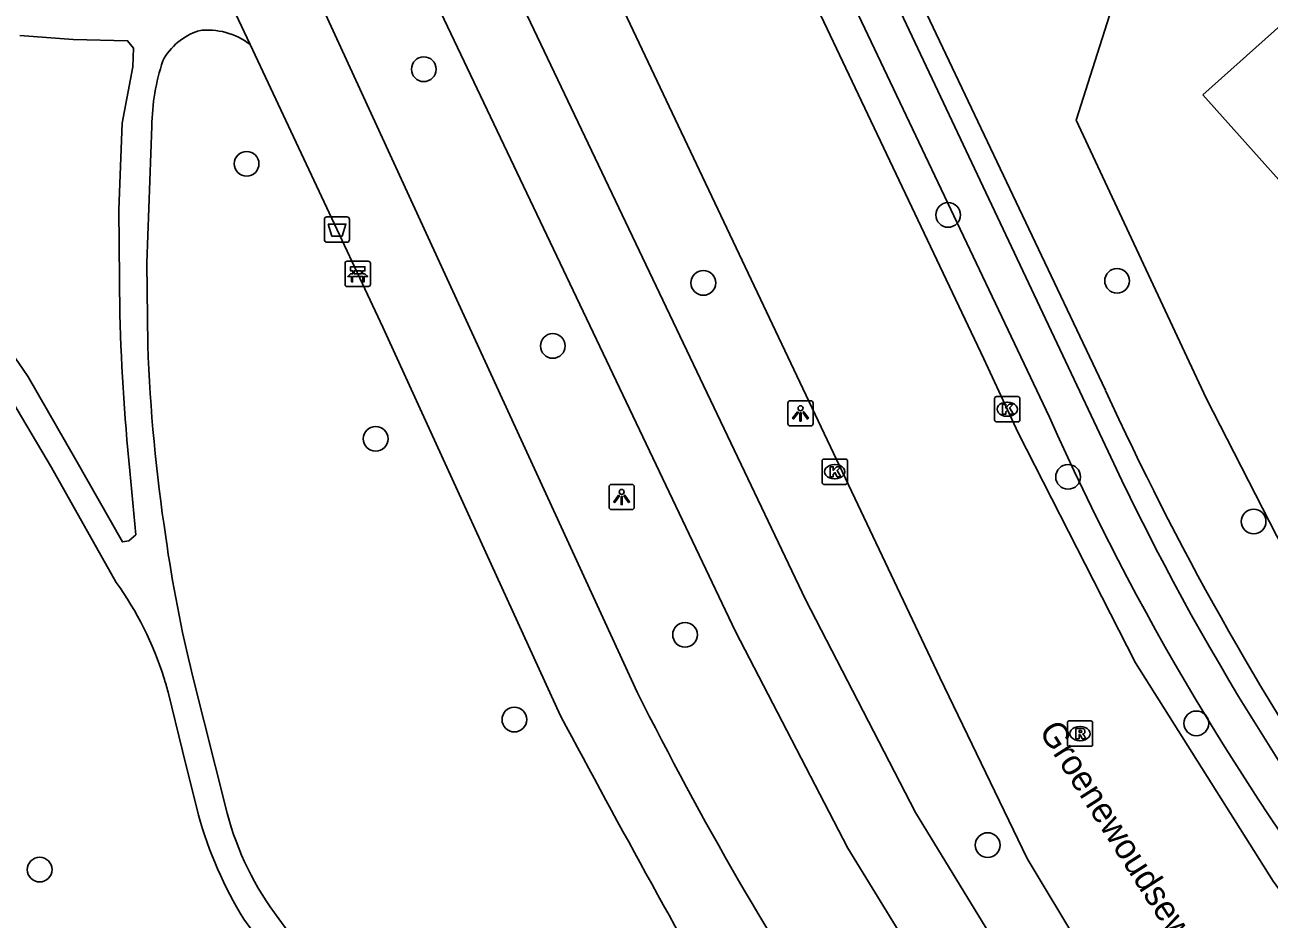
# Model space of a CAD drawing. Extents: x 159280 to 160375, y 384531 to 385872.
# Drawn here: x 159388.99 to 159438.21, y 385185.4 to 385220.77 of the extents above; entities that cross this region are included whole.
import ezdxf

# ---------------------------------------------------------------- set-up
doc = ezdxf.new("R2010")
doc.units = 0
for name, color, linetype in [('IMGEO_Afvalbak', 7, 'Continuous'), ('IMGEO_Bank', 7, 'Continuous'), ('IMGEO_Boom', 7, 'Continuous'), ('IMGEO_Fietspad_open', 7, 'Continuous'), ('IMGEO_Groenvoorziening', 7, 'Continuous'), ('IMGEO_Hek', 7, 'Continuous'), ('IMGEO_Kolk', 7, 'Continuous'), ('IMGEO_Lichtpunt', 7, 'Continuous'), ('IMGEO_Openbare_ruimte_label', 7, 'Continuous'), ('IMGEO_Pand_vergunning_verleend', 7, 'Continuous'), ('IMGEO_Rijbaan_lokaal_open', 7, 'Continuous'), ('IMGEO_Rioolput', 7, 'Continuous'), ('IMGEO_Voetpad_halfverhard', 7, 'Continuous'), ('IMGEO_Voetpad_open', 7, 'Continuous')]:
    doc.layers.add(name, color=color, linetype=linetype)

msp = doc.modelspace()

# ---------------------------------------------------------------- linework, layer by layer
at = {"layer": 'IMGEO_Afvalbak'}
for p, q in [((159400.841, 385212.278), (159400.841, 385213.078)), ((159400.841, 385213.078), (159400.841, 385212.278)), ((159400.941, 385213.178), (159401.731, 385213.178)), ((159401.731, 385213.178), (159400.941, 385213.178)), ((159401.831, 385213.078), (159401.831, 385212.278)), ((159401.831, 385212.278), (159401.831, 385213.078)), ((159401.731, 385212.178), (159400.941, 385212.178)), ((159400.941, 385212.178), (159401.731, 385212.178))]:
    msp.add_line(p, q, dxfattribs=at)
msp.add_lwpolyline([(159400.984, 385212.892), (159401.688, 385212.892), (159401.539, 385212.422), (159401.133, 385212.422), (159400.984, 385212.892)], dxfattribs=at)
for centre, start, end in [((159400.941, 385213.078), 90, 180), ((159400.941, 385213.078), 90, 180), ((159401.731, 385213.078), 0, 90), ((159401.731, 385213.078), 360, 90), ((159400.941, 385212.278), 180, 270), ((159400.941, 385212.278), 180, 270), ((159401.731, 385212.278), 270, 0), ((159401.731, 385212.278), 270, 0)]:
    msp.add_arc(centre, 0.1, start, end, dxfattribs=at)
at = {"layer": 'IMGEO_Bank'}
for p, q in [((159401.659, 385210.5), (159401.659, 385211.341)), ((159401.659, 385211.341), (159401.659, 385210.5)), ((159401.734, 385211.425), (159402.575, 385211.425)), ((159402.575, 385211.425), (159401.734, 385211.425)), ((159401.968, 385210.931), (159401.968, 385211.037)), ((159402.012, 385211.037), (159402.012, 385210.931)), ((159402.3, 385211.043), (159402.018, 385211.043)), ((159402.306, 385210.931), (159402.306, 385211.037)), ((159402.35, 385211.037), (159402.35, 385210.931)), ((159402.659, 385211.35), (159402.659, 385210.509)), ((159402.659, 385210.509), (159402.659, 385211.35)), ((159402.356, 385210.823), (159401.963, 385210.823)), ((159402.018, 385210.925), (159402.3, 385210.925)), ((159402.584, 385210.425), (159401.743, 385210.425)), ((159401.743, 385210.425), (159402.584, 385210.425))]:
    msp.add_line(p, q, dxfattribs=at)
for points in [[(159401.962, 385211.043), (159401.876, 385211.043), (159401.876, 385211.204), (159402.439, 385211.204), (159402.439, 385211.043), (159402.356, 385211.043)], [(159401.906, 385210.823), (159401.764, 385210.823), (159401.876, 385210.925), (159401.962, 385210.925)], [(159401.956, 385210.816), (159401.956, 385210.609), (159401.913, 385210.609), (159401.913, 385210.816)], [(159402.356, 385210.925), (159402.439, 385210.925), (159402.551, 385210.823), (159402.412, 385210.823)], [(159402.406, 385210.816), (159402.406, 385210.609), (159402.362, 385210.609), (159402.362, 385210.816)]]:
    msp.add_lwpolyline(points, dxfattribs=at)
for centre, radius, start, end in [((159401.737, 385211.347), 0.0779, 92.4484, 184.2845), ((159401.737, 385211.347), 0.0779, 92.4484, 184.2845), ((159401.961, 385211.036), 0.00671, 2.8957, 87.1043), ((159402.018, 385211.036), 0.00671, 92.8957, 177.1043), ((159402.3, 385211.036), 0.00671, 2.8957, 87.1043), ((159402.357, 385211.036), 0.00671, 92.8957, 177.1043), ((159402.581, 385211.347), 0.0779, 2.4484, 94.2845), ((159402.581, 385211.347), 0.0779, 2.4484, 94.2845), ((159401.737, 385210.503), 0.0779, 182.4484, 274.2845), ((159401.737, 385210.503), 0.0779, 182.4484, 274.2845), ((159401.906, 385210.816), 0.00671, 2.8957, 87.1043), ((159401.963, 385210.816), 0.00671, 92.8957, 177.1043), ((159401.961, 385210.932), 0.00671, 272.8957, 357.1043), ((159402.018, 385210.932), 0.00671, 182.8957, 267.1043), ((159402.3, 385210.932), 0.00671, 272.8957, 357.1043), ((159402.357, 385210.932), 0.00671, 182.8957, 267.1043), ((159402.355, 385210.816), 0.00671, 2.8957, 87.1043), ((159402.412, 385210.816), 0.00671, 92.8957, 177.1043), ((159402.581, 385210.503), 0.0779, 272.4484, 4.2845), ((159402.581, 385210.503), 0.0779, 272.4484, 4.2845)]:
    msp.add_arc(centre, radius, start, end, dxfattribs=at)
at = {"layer": 'IMGEO_Boom'}
for centre in [(159404.771, 385219.02), (159397.761, 385215.279), (159425.516, 385213.257), (159415.83, 385210.568), (159432.2, 385210.65), (159409.875, 385208.075), (159402.867, 385204.4), (159430.262, 385202.895), (159437.602, 385201.129), (159415.108, 385196.648), (159408.356, 385193.294), (159435.335, 385193.143), (159427.08, 385188.328), (159389.574, 385187.359)]:
    msp.add_circle(centre, 0.489, dxfattribs=at)
at = {"layer": 'IMGEO_Fietspad_open'}
for points in [[(159419.772, 385229.512), (159419.822, 385229.373), (159432.073, 385203.428)], [(159429.521, 385205.255), (159420.205, 385224.888), (159419.956, 385224.766)], [(159408.187, 385222.576), (159419.876, 385198.049), (159424.225, 385189.616), (159427.314, 385184.565), (159432.478, 385177.08), (159436.179, 385172.483)], [(159405.443, 385221.27), (159417.105, 385196.774), (159421.543, 385188.209), (159424.758, 385182.98), (159430.05, 385175.255), (159434.187, 385170.106), (159442.865, 385159.598), (159444.527, 385157.561), (159454.301, 385145.739), (159456.65, 385142.935), (159463.095, 385135.058), (159465.215, 385132.533), (159468.191, 385128.94)]]:
    msp.add_lwpolyline(points, dxfattribs=at)
for centre, radius, start, end in [((159525.889, 385248.134), 105.477, 203.9866, 217.61266), ((159522.981, 385246.186), 100.462, 205.18956, 218.82579)]:
    msp.add_arc(centre, radius, start, end, dxfattribs=at)
at = {"layer": 'IMGEO_Groenvoorziening'}
msp.add_lwpolyline([(159469.674, 385166.696), (159467.724, 385165.189), (159465.252, 385165.282), (159445.93, 385188.732), (159443.21, 385192.716), (159441.573, 385195.295), (159438.506, 385200.578), (159435.719, 385206.014), (159430.587, 385217.007), (159436.757, 385236.409)], dxfattribs=at)
at = {"layer": 'IMGEO_Hek'}
msp.add_lwpolyline([(159467.724, 385165.189), (159465.252, 385165.282), (159445.93, 385188.732), (159443.21, 385192.716), (159441.573, 385195.295), (159438.506, 385200.578), (159435.719, 385206.014), (159430.587, 385217.007), (159436.757, 385236.409)], dxfattribs=at)
at = {"layer": 'IMGEO_Kolk'}
for p, q in [((159427.427, 385206.072), (159428.279, 385206.072)), ((159427.352, 385205.146), (159427.352, 385205.998)), ((159427.84, 385205.852), (159427.865, 385205.852)), ((159428.353, 385205.998), (159428.353, 385205.146)), ((159428.279, 385205.072), (159427.427, 385205.072)), ((159427.863, 385205.292), (159427.838, 385205.292)), ((159420.605, 385203.598), (159421.457, 385203.598)), ((159420.53, 385202.672), (159420.53, 385203.524)), ((159421.018, 385203.378), (159421.043, 385203.378)), ((159421.531, 385203.524), (159421.531, 385202.672)), ((159421.457, 385202.598), (159420.605, 385202.598)), ((159421.041, 385202.818), (159421.016, 385202.818))]:
    msp.add_line(p, q, dxfattribs=at)
for points in [[(159427.427, 385206.072), (159428.279, 385206.072)], [(159427.352, 385205.146), (159427.352, 385205.998)], [(159427.673, 385205.772), (159427.796, 385205.772), (159427.796, 385205.621), (159427.926, 385205.772), (159428.09, 385205.772), (159427.944, 385205.621), (159428.097, 385205.372), (159427.945, 385205.372), (159427.86, 385205.536), (159427.796, 385205.469), (159427.796, 385205.372), (159427.673, 385205.372), (159427.673, 385205.772)], [(159428.353, 385205.998), (159428.353, 385205.146)], [(159428.279, 385205.072), (159427.427, 385205.072)], [(159420.605, 385203.598), (159421.457, 385203.598)], [(159420.53, 385202.672), (159420.53, 385203.524)], [(159420.851, 385203.298), (159420.974, 385203.298), (159420.974, 385203.147), (159421.104, 385203.298), (159421.268, 385203.298), (159421.122, 385203.147), (159421.275, 385202.898), (159421.123, 385202.898), (159421.038, 385203.062), (159420.974, 385202.995), (159420.974, 385202.898), (159420.851, 385202.898), (159420.851, 385203.298)], [(159421.531, 385203.524), (159421.531, 385202.672)], [(159421.457, 385202.598), (159420.605, 385202.598)]]:
    msp.add_lwpolyline(points, dxfattribs=at)
for centre, start, end in [((159427.429, 385205.996), 91.552, 178.448), ((159427.429, 385205.996), 91.552, 178.448), ((159428.277, 385205.996), 1.552, 88.448), ((159428.277, 385205.996), 1.552, 88.448), ((159427.429, 385205.148), 181.552, 268.448), ((159427.429, 385205.148), 181.552, 268.448), ((159428.277, 385205.148), 271.552, 358.448), ((159428.277, 385205.148), 271.552, 358.448), ((159420.607, 385203.522), 91.552, 178.448), ((159420.607, 385203.522), 91.552, 178.448), ((159421.455, 385203.522), 1.552, 88.448), ((159421.455, 385203.522), 1.552, 88.448), ((159420.607, 385202.674), 181.552, 268.448), ((159420.607, 385202.674), 181.552, 268.448), ((159421.455, 385202.674), 271.552, 358.448), ((159421.455, 385202.674), 271.552, 358.448)]:
    msp.add_arc(centre, 0.0765, start, end, dxfattribs=at)
for centre, major_axis, ratio, start_param, end_param in [((159427.839, 385205.572), (-0.387, 0.002), 0.722429, 4.712389, 7.853982), ((159427.864, 385205.572), (-0.39, 0.002), 0.717154, 1.570796, 4.712389), ((159421.017, 385203.098), (-0.387, 0.002), 0.722429, 4.712389, 7.853982), ((159421.042, 385203.098), (-0.39, 0.002), 0.717154, 1.570796, 4.712389)]:
    msp.add_ellipse(centre, major_axis=major_axis, ratio=ratio, start_param=start_param, end_param=end_param, dxfattribs=at)
at = {"layer": 'IMGEO_Lichtpunt'}
for p, q in [((159419.178, 385205.81), (159419.178, 385205.003)), ((159419.178, 385205.81), (159419.178, 385205.003)), ((159420.08, 385205.905), (159419.272, 385205.905)), ((159420.08, 385205.905), (159419.272, 385205.905)), ((159420.174, 385205.003), (159420.174, 385205.81)), ((159420.174, 385205.003), (159420.174, 385205.81)), ((159419.272, 385204.909), (159420.08, 385204.909)), ((159419.272, 385204.909), (159420.08, 385204.909)), ((159413.003, 385202.597), (159412.195, 385202.597)), ((159413.003, 385202.597), (159412.195, 385202.597)), ((159412.101, 385202.502), (159412.101, 385201.695)), ((159412.101, 385202.502), (159412.101, 385201.695)), ((159413.097, 385201.695), (159413.097, 385202.502)), ((159413.097, 385201.695), (159413.097, 385202.502)), ((159412.195, 385201.601), (159413.003, 385201.601)), ((159412.195, 385201.601), (159413.003, 385201.601))]:
    msp.add_line(p, q, dxfattribs=at)
for points in [[(159419.552, 385205.474), (159419.591, 385205.446), (159419.403, 385205.184), (159419.365, 385205.211), (159419.552, 385205.474)], [(159419.654, 385205.426), (159419.701, 385205.426), (159419.701, 385205.104), (159419.654, 385205.104), (159419.654, 385205.426)], [(159419.764, 385205.446), (159419.802, 385205.473), (159419.989, 385205.211), (159419.95, 385205.183), (159419.764, 385205.446)], [(159412.475, 385202.166), (159412.514, 385202.138), (159412.326, 385201.876), (159412.288, 385201.903), (159412.475, 385202.166)], [(159412.577, 385202.118), (159412.624, 385202.118), (159412.624, 385201.796), (159412.577, 385201.796), (159412.577, 385202.118)], [(159412.687, 385202.138), (159412.725, 385202.165), (159412.912, 385201.903), (159412.873, 385201.875), (159412.687, 385202.138)]]:
    msp.add_lwpolyline(points, dxfattribs=at)
for centre in [(159419.677, 385205.608), (159412.6, 385202.3)]:
    msp.add_circle(centre, 0.0994, dxfattribs=at)
for centre, start, end in [((159419.272, 385205.81), 90, 180), ((159419.272, 385205.81), 90, 180), ((159420.08, 385205.81), 0, 90), ((159420.08, 385205.81), 0, 90), ((159419.272, 385205.003), 180, 270), ((159419.272, 385205.003), 180, 270), ((159420.08, 385205.003), 270, 0), ((159420.08, 385205.003), 270, 360), ((159412.195, 385202.502), 90, 180), ((159412.195, 385202.502), 90, 180), ((159413.003, 385202.502), 0, 90), ((159413.003, 385202.502), 0, 90), ((159412.195, 385201.695), 180, 270), ((159412.195, 385201.695), 180, 270), ((159413.003, 385201.695), 270, 0), ((159413.003, 385201.695), 270, 360)]:
    msp.add_arc(centre, 0.0946, start, end, dxfattribs=at)
at = {"layer": 'IMGEO_Pand_vergunning_verleend'}
msp.add_lwpolyline([(159435.597, 385218.004), (159449.147, 385230.123), (159454.993, 385223.69), (159454.244, 385223.08), (159456.222, 385220.649), (159450.569, 385216.051), (159452.046, 385213.701), (159450.912, 385212.989), (159461.526, 385196.101), (159452.727, 385190.571), (159440.305, 385210.334), (159441.501, 385211.402), (159435.597, 385218.004)], dxfattribs=at)
at = {"layer": 'IMGEO_Rijbaan_lokaal_open'}
for points in [[(159418.994, 385224.295), (159426.924, 385207.568), (159428.293, 385204.641), (159432.934, 385195.543), (159438.369, 385186.896), (159441.416, 385182.704), (159446.916, 385176.066), (159451.729, 385170.222), (159453.376, 385168.243)], [(159437.674, 385173.526), (159434.559, 385178.332), (159432.725, 385180.994), (159428.641, 385187.804), (159425.182, 385194.952), (159414.477, 385217.542), (159411.394, 385224.077)]]:
    msp.add_lwpolyline(points, dxfattribs=at)
at = {"layer": 'IMGEO_Rioolput'}
for p, q in [((159430.308, 385193.238), (159431.16, 385193.238)), ((159430.233, 385192.312), (159430.233, 385193.164)), ((159430.721, 385193.018), (159430.746, 385193.018)), ((159431.234, 385193.164), (159431.234, 385192.312)), ((159430.744, 385192.458), (159430.719, 385192.458)), ((159431.16, 385192.238), (159430.308, 385192.238))]:
    msp.add_line(p, q, dxfattribs=at)
for points in [[(159430.308, 385193.238), (159431.16, 385193.238)], [(159430.233, 385192.312), (159430.233, 385193.164)], [(159430.822, 385192.936), (159430.57, 385192.938), (159430.57, 385192.538)], [(159430.748, 385192.857), (159430.694, 385192.857), (159430.694, 385192.776)], [(159430.694, 385192.776), (159430.746, 385192.776)], [(159431.234, 385193.164), (159431.234, 385192.312)], [(159430.57, 385192.538), (159430.694, 385192.538), (159430.694, 385192.7), (159430.705, 385192.7)], [(159430.752, 385192.671), (159430.823, 385192.538), (159430.963, 385192.538), (159430.898, 385192.664)], [(159431.16, 385192.238), (159430.308, 385192.238)]]:
    msp.add_lwpolyline(points, dxfattribs=at)
for centre, radius, start, end in [((159430.31, 385193.162), 0.0765, 91.552, 178.448), ((159430.31, 385193.162), 0.0765, 91.552, 178.448), ((159431.158, 385193.162), 0.0765, 1.552, 88.448), ((159431.158, 385193.162), 0.0765, 1.552, 88.448), ((159430.73, 385192.965), 0.19, 274.7715, 282.9687), ((159430.754, 385192.761), 0.0964, 77.0061, 93.1865), ((159430.768, 385192.818), 0.0378, 276.6634, 79.6772), ((159430.821, 385192.826), 0.109, 350.3612, 89.416), ((159430.819, 385192.826), 0.112, 277.5842, 350.9817), ((159430.31, 385192.314), 0.0765, 181.552, 268.448), ((159430.31, 385192.314), 0.0765, 181.552, 268.448), ((159430.704, 385192.647), 0.0533, 26.0293, 88.6989), ((159430.803, 385192.611), 0.108, 29.5134, 73.7905), ((159431.158, 385192.314), 0.0765, 271.552, 358.448), ((159431.158, 385192.314), 0.0765, 271.552, 358.448)]:
    msp.add_arc(centre, radius, start, end, dxfattribs=at)
for centre, major_axis, ratio, start_param, end_param in [((159430.72, 385192.738), (-0.387, 0.002), 0.722429, 4.712389, 7.853982), ((159430.745, 385192.738), (-0.39, 0.002), 0.717154, 1.570796, 4.712389)]:
    msp.add_ellipse(centre, major_axis=major_axis, ratio=ratio, start_param=start_param, end_param=end_param, dxfattribs=at)
at = {"layer": 'IMGEO_Voetpad_halfverhard'}
for points in [[(159413.219, 385194.379), (159400.356, 385222.353), (159395.612, 385232.161)], [(159396.931, 385222.103), (159397.326, 385221.219), (159397.898, 385220)], [(159388.796, 385220.355), (159390.903, 385220.201), (159393.05, 385220.147), (159393.293, 385219.854), (159393.26, 385219.115), (159392.838, 385216.887), (159392.71, 385213.468), (159392.747, 385209.32)], [(159397.898, 385220), (159403.148, 385208.818), (159410.18, 385193.443)], [(159393.852, 385208.101), (159393.818, 385211.362), (159394.007, 385216.765)], [(159388.088, 385206.559), (159390.044, 385203.266), (159392.603, 385198.719)], [(159393.18, 385202.717), (159393.383, 385200.604), (159393.102, 385200.362), (159392.852, 385200.32), (159391.004, 385203.563), (159389.117, 385206.858)], [(159396.988, 385189.594), (159395.62, 385195.038)], [(159394.654, 385194.382), (159395.23, 385192.054), (159395.86, 385189.506)], [(159397.655, 385185.4), (159402.336, 385178.984)], [(159404.056, 385178.52), (159401.53, 385181.999), (159399.035, 385185.407)]]:
    msp.add_lwpolyline(points, dxfattribs=at)
for centre, radius, start, end in [((159396.67, 385218.141), 2.536, 108.5193, 151.3612), ((159396.23, 385217.842), 2.727, 52.2956, 97.6908), ((159403.091, 385216.562), 9.086, 162.0907, 178.7194), ((159318.108, 385158.66), 85.822, 34.16712, 41.54279), ((159480.623, 385211.767), 87.91, 181.59496, 185.90878), ((159460.918, 385210.562), 67.111, 182.10135, 188.6089), ((159449.242, 385208.225), 55.22, 188.0256, 193.8169), ((159381.856, 385190.983), 13.241, 17.4553, 35.7479), ((159381.62, 385190.917), 13.487, 14.8892, 17.4238), ((159533.808, 385254.465), 134.73, 206.48581, 213.6776), ((159882.39, 385445.449), 535.247, 208.08768, 209.70744), ((159411.025, 385193.69), 15.732, 195.4251, 211.8014), ((159408.759, 385192.755), 12.188, 195.0312, 217.0763)]:
    msp.add_arc(centre, radius, start, end, dxfattribs=at)
at = {"layer": 'IMGEO_Voetpad_open'}
msp.add_lwpolyline([(159431.745, 385206.318), (159421.894, 385227.072)], dxfattribs=at)
msp.add_arc((159541.904, 385256.643), 121.11, 204.55282, 214.09608, dxfattribs=at)

# ---------------------------------------------------------------- texts
at = {"layer": 'IMGEO_Openbare_ruimte_label'}
msp.add_text('Groenewoudseweg', height=1, rotation=302.5459, dxfattribs=at).set_placement((159429.083, 385192.843))

doc.saveas('drawing.dxf')
